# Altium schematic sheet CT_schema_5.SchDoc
size 293 x 258 mm
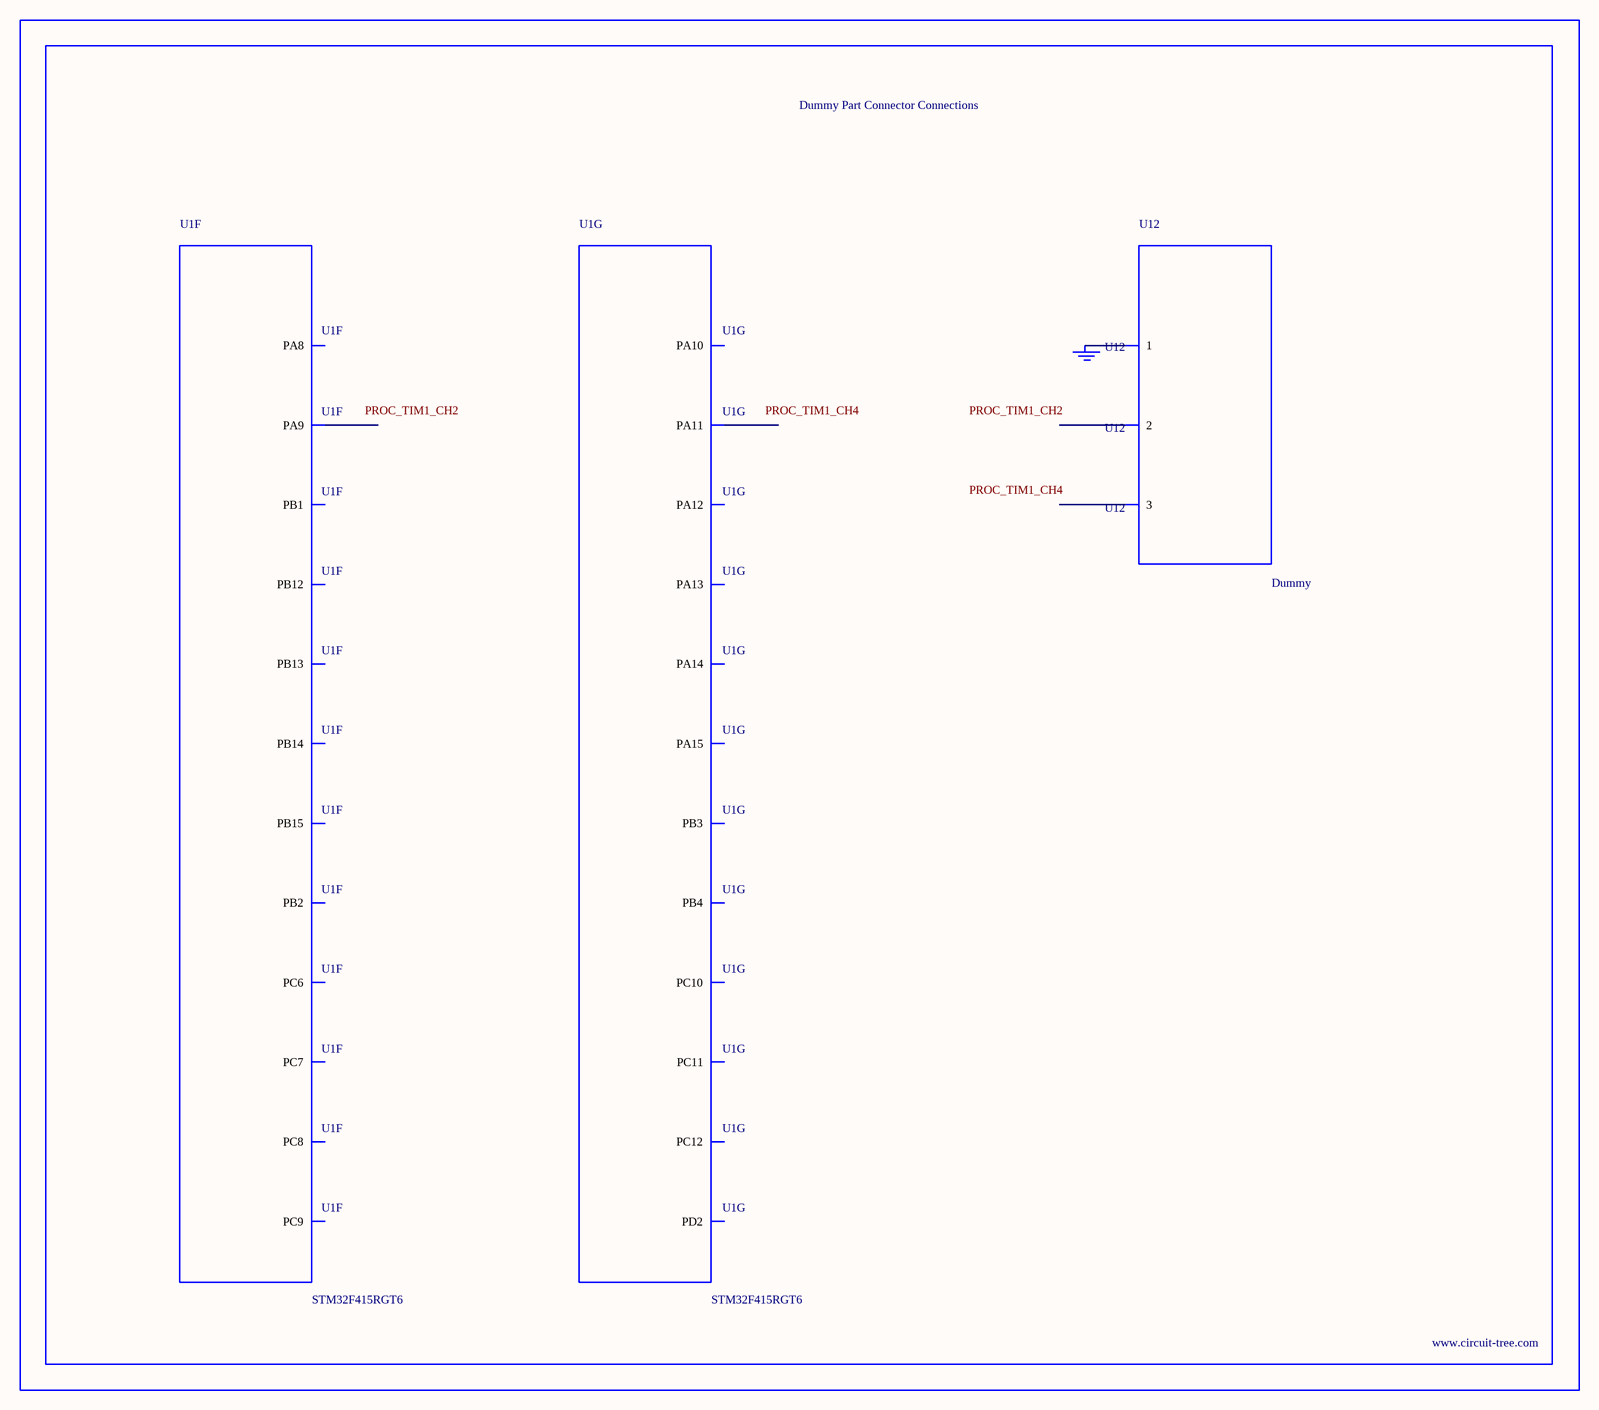
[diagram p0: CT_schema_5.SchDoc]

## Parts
BORDER4  (no value)
GND_INSTANCE_4_0  (no value)
U1  STM32F415RGT6  [LQFP64]  (parts F,G of 7)
U12  Dummy  [DUMMY_PACKAGE_138]

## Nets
NetGND_INSTANCE_4_0_0: GND_INSTANCE_4_0.0(GND) U12.1

Not connected (* = marked no-connect by the designer): U1 27(PB1) 28(PB2) 33(PB12) 34(PB13) 35(PB14) 36(PB15) 37(PC6) 38(PC7) 39(PC8) 40(PC9) 41(PA8) 42(PA9) 43(PA10) 44(PA11) 45(PA12) 46(PA13) 49(PA14) 50(PA15) 51(PC10) 52(PC11) 53(PC12) 54(PD2) 55(PB3) 56(PB4); U12 2 3

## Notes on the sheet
- Labels drawn without touching a wire or pin: PROC_TIM1_CH2, PROC_TIM1_CH4

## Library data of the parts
BORDER4 = BORDER_PAGE4
GND_INSTANCE_4_0 = GND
